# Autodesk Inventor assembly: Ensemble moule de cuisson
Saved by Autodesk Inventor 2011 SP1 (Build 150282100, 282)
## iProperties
Created: 2010-12
Part Number: Ensemble moule de cuisson
Document SubType Name: Assembly
Designer: eric
Author: eric
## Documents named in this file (4)
- D:\eduinventor\maquettesaip2011\machineàpain\Workspace\Ensemble moule de cuisson.iam
- D:\eduinventor\maquettesaip2011\machineàpain\Workspace\moule de cuisson.ipt
- D:\eduinventor\maquettesaip2011\machineàpain\Workspace\poignee de moule.ipt
- D:\eduinventor\maquettesaip2011\machineàpain\Workspace\Symétriepoignee de moule.ipt
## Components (3 placed, 3 different names)
1. moule de cuisson:1
2. poignee de moule:1
3. Symétriepoignee de moule:1
